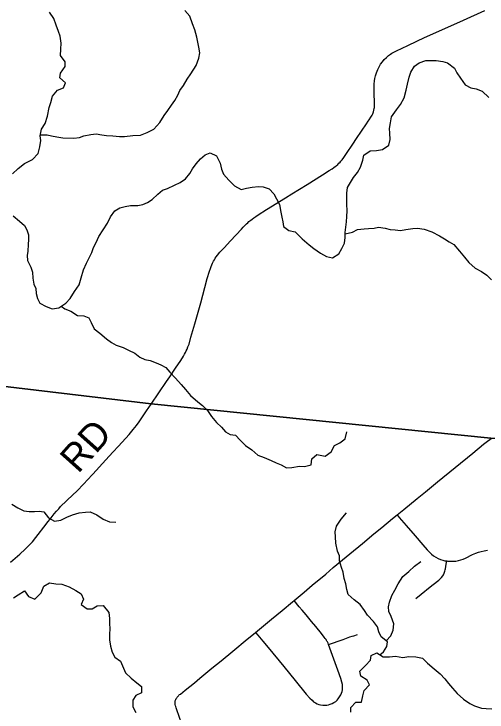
# Model space of a CAD drawing. Extents: x 0 to 34, y 0 to 22.
# Drawn here: x 6.899 to 7.881, y 18.658 to 20.107 of the extents above; entities that cross this region are included whole.
import ezdxf

# ---------------------------------------------------------------- set-up
doc = ezdxf.new("R2010")
doc.units = 0
for name, color, linetype in [('GM_X_Major_River', 7, 'Continuous'), ('GM_X_Minor_River', 7, 'Continuous'), ('GM_X_Township_Road', 7, 'Continuous'), ('GM_X_Township_Road_Text', 7, 'Continuous')]:
    doc.layers.add(name, color=color, linetype=linetype)

msp = doc.modelspace()

# ---------------------------------------------------------------- linework, layer by layer
at = {"layer": 'GM_X_Major_River'}
for points in [[(7.6639, 19.8257), (7.6766, 19.8342), (7.6795, 19.8463), (7.6787, 19.8592), (7.6785, 19.8691), (7.6806, 19.8809), (7.6824, 19.8934), (7.6926, 19.9076), (7.7008, 19.9185), (7.7084, 19.9328), (7.7125, 19.9483), (7.7158, 19.9607), (7.7192, 19.9755), (7.7228, 19.9857), (7.7303, 19.9981), (7.7399, 20.0051), (7.7533, 20.0101), (7.7655, 20.0102), (7.7753, 20.0097), (7.7886, 20.0082), (7.7988, 20.0054), (7.8129, 19.994), (7.818, 19.9844), (7.8258, 19.9732), (7.835, 19.9597), (7.847, 19.953), (7.8583, 19.9509), (7.8707, 19.9461), (7.8841, 19.9329)], [(6.9293, 19.6485), (6.9291, 19.639), (6.9281, 19.6283), (6.9274, 19.6147), (6.9261, 19.6052), (6.9266, 19.5953), (6.9339, 19.5814), (6.9375, 19.5707), (6.9383, 19.5585), (6.9403, 19.5463), (6.9439, 19.5368), (6.9452, 19.5268), (6.9473, 19.5165), (6.9528, 19.5065), (6.9655, 19.4998), (6.9779, 19.495), (6.992, 19.497), (7.0067, 19.5069), (7.0152, 19.5166), (7.0246, 19.5305), (7.0344, 19.5444), (7.0386, 19.5591), (7.0431, 19.5761), (7.0495, 19.5893), (7.0542, 19.5991), (7.0602, 19.6115), (7.0642, 19.6224), (7.0694, 19.6322), (7.075, 19.645), (7.084, 19.6585), (7.0927, 19.6728), (7.099, 19.6859), (7.108, 19.6983), (7.1188, 19.7041), (7.1299, 19.707), (7.1409, 19.709), (7.1561, 19.7094), (7.1664, 19.7115), (7.176, 19.7151), (7.1856, 19.7214), (7.1972, 19.7325), (7.2073, 19.7407), (7.2172, 19.7447), (7.2318, 19.7512), (7.2437, 19.757), (7.2545, 19.7644), (7.2638, 19.7756), (7.2694, 19.7854), (7.2768, 19.7959), (7.2858, 19.8059), (7.2958, 19.8145), (7.3058, 19.8184), (7.3193, 19.8125), (7.3266, 19.7971), (7.3293, 19.7845), (7.3336, 19.7741), (7.3448, 19.7621), (7.3566, 19.7497), (7.3705, 19.7422), (7.3816, 19.745), (7.3934, 19.747), (7.406, 19.7487), (7.4158, 19.7481), (7.4283, 19.7436), (7.4379, 19.7332), (7.4437, 19.7232), (7.4496, 19.7112), (7.453, 19.6952), (7.4551, 19.6849), (7.4567, 19.6754), (7.4584, 19.6654), (7.4693, 19.6572), (7.4825, 19.6543), (7.4973, 19.6399), (7.5115, 19.6278), (7.5212, 19.62), (7.5347, 19.6106), (7.5478, 19.6035), (7.5599, 19.601), (7.5733, 19.609), (7.5793, 19.6203), (7.5845, 19.6312), (7.5862, 19.6426), (7.5865, 19.6529), (7.5875, 19.6646), (7.5888, 19.6752), (7.5895, 19.6863), (7.5901, 19.6984), (7.59, 19.7121), (7.5896, 19.7254), (7.5894, 19.7349), (7.5912, 19.7463), (7.5975, 19.7572), (7.6038, 19.7673), (7.6116, 19.7774), (7.6179, 19.7887), (7.6228, 19.8034), (7.6249, 19.8136), (7.6384, 19.8228), (7.6509, 19.8233), (7.6639, 19.8257)], [(6.8971, 19.6879), (6.9105, 19.6766), (6.9206, 19.668), (6.9257, 19.6584), (6.9293, 19.6485)]]:
    msp.add_lwpolyline(points, dxfattribs=at)
at = {"layer": 'GM_X_Minor_River'}
for points in [[(6.9536, 19.856), (6.9675, 19.8555), (6.977, 19.8539), (6.9876, 19.8519), (7.0001, 19.8495), (7.0228, 19.8492), (7.0346, 19.8506), (7.0441, 19.8539), (7.0586, 19.8568), (7.0696, 19.8582), (7.081, 19.8561), (7.0912, 19.8541), (7.1041, 19.8536), (7.1178, 19.8523), (7.128, 19.8526), (7.1455, 19.8546), (7.1615, 19.8548), (7.1756, 19.8607), (7.1889, 19.8674), (7.2013, 19.8817), (7.2102, 19.8961), (7.2182, 19.9062), (7.2256, 19.9175), (7.2325, 19.9273), (7.2387, 19.9379), (7.2434, 19.9477), (7.2504, 19.9579), (7.2581, 19.9711), (7.2658, 19.982), (7.2767, 19.9998), (7.2826, 20.0149), (7.2846, 20.0259), (7.2824, 20.0373), (7.2807, 20.048), (7.2785, 20.0582), (7.2741, 20.0735), (7.2694, 20.0861), (7.2635, 20.1017), (7.2537, 20.114)], [(6.8955, 19.7747), (6.9074, 19.7863), (6.9205, 19.7964), (6.9373, 19.8046), (6.9492, 19.8174), (6.9524, 19.8306), (6.9544, 19.8439), (6.953, 19.8538), (6.9562, 19.8674), (6.9636, 19.8795), (6.9683, 19.8946), (6.972, 19.9125), (6.9755, 19.9227), (6.9787, 19.9363), (6.9891, 19.9487), (7.0017, 19.9535), (7.006, 19.9637), (6.9943, 19.9741), (6.9952, 19.984), (7.0052, 19.9972), (7.0054, 20.007), (6.9953, 20.0201), (6.9962, 20.0337), (6.9967, 20.0459), (6.9946, 20.0607), (6.9909, 20.0703), (6.9865, 20.0832), (6.9814, 20.097), (6.9728, 20.1104)], [(7.5864, 19.6502), (7.6017, 19.6542), (7.6116, 19.6594), (7.6253, 19.6607), (7.6348, 19.6618), (7.6462, 19.6624), (7.6557, 19.6642), (7.6693, 19.6625), (7.6799, 19.6597), (7.6898, 19.6588), (7.7008, 19.6576), (7.7122, 19.6593), (7.7266, 19.6618), (7.7365, 19.6621), (7.7502, 19.6604), (7.7664, 19.6545), (7.7823, 19.646), (7.7921, 19.6398), (7.8022, 19.634), (7.812, 19.6282), (7.8233, 19.6148), (7.8341, 19.6017), (7.8431, 19.591), (7.8562, 19.5794), (7.8691, 19.5721), (7.88, 19.5644), (7.8897, 19.5551)], [(6.9971, 19.5004), (7.0042, 19.4946), (7.017, 19.4899), (7.0306, 19.481), (7.0439, 19.4805), (7.0541, 19.4762), (7.0593, 19.4663), (7.0652, 19.4533), (7.0772, 19.4444), (7.0911, 19.4325), (7.1013, 19.4251), (7.1111, 19.4197), (7.1255, 19.4146), (7.1364, 19.4088), (7.15, 19.4029), (7.1598, 19.3948), (7.1707, 19.3901), (7.1813, 19.3874), (7.1938, 19.3827), (7.2036, 19.3787), (7.2142, 19.3733), (7.2224, 19.3637), (7.2344, 19.351), (7.2456, 19.3376), (7.255, 19.3273), (7.2655, 19.315), (7.2801, 19.3023), (7.2903, 19.2942), (7.3004, 19.2838), (7.309, 19.2712), (7.3195, 19.2589), (7.3292, 19.2497), (7.3375, 19.2397), (7.3473, 19.2339), (7.3583, 19.233), (7.368, 19.2223), (7.3796, 19.2115), (7.3928, 19.2022), (7.4052, 19.1911), (7.4181, 19.1864), (7.4324, 19.1805), (7.443, 19.1751), (7.4532, 19.1711), (7.4641, 19.1649), (7.4755, 19.1659), (7.4915, 19.1688), (7.5021, 19.1679), (7.5154, 19.1716), (7.5171, 19.1837), (7.5275, 19.1927), (7.5445, 19.1891), (7.5571, 19.1981), (7.5641, 19.2113), (7.5752, 19.2168), (7.5863, 19.2255), (7.5899, 19.2395)], [(6.8946, 19.0894), (6.907, 19.0824), (6.9191, 19.0758), (6.9305, 19.0746), (6.9411, 19.0748), (6.951, 19.0751), (6.9608, 19.0738), (6.9705, 19.0612), (6.983, 19.0542), (6.9959, 19.0563), (7.0085, 19.0627), (7.0204, 19.0675), (7.0344, 19.0719), (7.047, 19.0728), (7.0572, 19.0739), (7.0705, 19.0676), (7.0836, 19.0588), (7.0969, 19.0533), (7.1105, 19.0524)], [(7.6585, 18.7772), (7.6657, 18.7835), (7.673, 18.7944), (7.6743, 18.8039), (7.6608, 18.8147), (7.6559, 18.825), (7.653, 18.8349), (7.6452, 18.846), (7.6328, 18.8595), (7.6261, 18.8691), (7.6171, 18.8813), (7.6047, 18.8913), (7.5927, 18.9021), (7.5898, 18.9124), (7.5873, 18.9242), (7.584, 18.9356), (7.5823, 18.9486), (7.5786, 18.9581), (7.5746, 18.9722), (7.5743, 18.9825), (7.5703, 18.9924), (7.5666, 19.0088), (7.5661, 19.0221), (7.5654, 19.032), (7.5682, 19.0441), (7.5779, 19.0588), (7.589, 19.0716)], [(7.6713, 18.8063), (7.6809, 18.8168), (7.686, 18.8285), (7.6869, 18.8414), (7.6818, 18.857), (7.6766, 18.867), (7.6759, 18.8768), (7.6779, 18.8863), (7.6834, 18.8999), (7.6892, 18.9116), (7.6962, 18.9245), (7.7059, 18.9396), (7.7185, 18.9497), (7.7301, 18.9613), (7.7435, 18.9707)], [(6.8976, 18.8956), (6.9075, 18.9016), (6.9209, 18.9102), (6.9287, 18.8979), (6.9424, 18.8929), (6.955, 18.906), (6.9609, 18.9196), (6.9727, 18.9263), (6.9856, 18.9246), (6.9981, 18.9234), (7.0136, 18.9179), (7.0272, 18.9105), (7.0381, 18.9039), (7.0429, 18.8928), (7.0386, 18.8815), (7.0507, 18.8726), (7.0609, 18.8729), (7.0716, 18.8785), (7.0842, 18.8798), (7.0958, 18.8649), (7.0971, 18.8523), (7.097, 18.8428), (7.0976, 18.8303), (7.0971, 18.8208), (7.097, 18.8083), (7.0991, 18.7949), (7.1024, 18.7824), (7.1083, 18.772), (7.1196, 18.7643), (7.1263, 18.7498), (7.1303, 18.7399), (7.142, 18.7287), (7.1536, 18.7191), (7.1634, 18.7114), (7.1632, 18.6981), (7.1514, 18.6929), (7.1456, 18.6831), (7.1458, 18.6694), (7.1517, 18.6576)], [(7.5978, 18.6582), (7.5979, 18.6677), (7.6083, 18.6789), (7.62, 18.6788), (7.6232, 18.6921), (7.6253, 18.7034), (7.6364, 18.7147), (7.6316, 18.7246), (7.6184, 18.7328), (7.6166, 18.7434), (7.6282, 18.7547), (7.6385, 18.766), (7.6402, 18.7755), (7.652, 18.781), (7.6652, 18.7733), (7.6781, 18.7727), (7.691, 18.7741), (7.7058, 18.7717), (7.7183, 18.7738), (7.7331, 18.7732), (7.7468, 18.77), (7.7573, 18.7597), (7.7712, 18.7481), (7.7832, 18.7377), (7.7933, 18.7277), (7.8004, 18.7174), (7.809, 18.7078), (7.8188, 18.6967), (7.8315, 18.6851), (7.8447, 18.6759), (7.8545, 18.6712), (7.8689, 18.6665), (7.8791, 18.6656), (7.8905, 18.6651)]]:
    msp.add_lwpolyline(points, dxfattribs=at)
at = {"layer": 'GM_X_Township_Road'}
msp.add_lwpolyline([(8.9, 19.1426), (8.9, 20.9), (4.4664, 20.9), (4.4684, 20.7448), (4.4849, 19.6021), (5.1411, 19.5203), (5.6889, 19.4592), (5.8809, 19.4409), (6.3561, 19.3959), (7.1834, 19.2978), (7.8888, 19.2268), (8.4186, 19.1875)], close=True, dxfattribs=at)
for points in [[(7.1836, 19.2972), (7.2156, 19.3439), (7.2226, 19.3541), (7.2342, 19.3718), (7.2448, 19.3879), (7.2504, 19.3969), (7.2525, 19.4006), (7.2548, 19.4045), (7.2565, 19.4079), (7.2581, 19.4112), (7.26, 19.4158), (7.261, 19.4187), (7.2621, 19.4217), (7.2662, 19.4361), (7.2742, 19.4635), (7.2865, 19.5072), (7.2949, 19.539), (7.3, 19.5576), (7.3046, 19.5731), (7.3065, 19.5788), (7.3078, 19.5824), (7.3094, 19.5862), (7.3109, 19.5898), (7.313, 19.5937), (7.3147, 19.5968), (7.3166, 19.5998), (7.3184, 19.6025), (7.3209, 19.6059), (7.326, 19.6121), (7.3348, 19.6217), (7.3484, 19.6362), (7.3708, 19.6604), (7.3748, 19.6644), (7.3786, 19.6684), (7.3814, 19.6711), (7.384, 19.6734), (7.3866, 19.6757), (7.3901, 19.6786), (7.3933, 19.6811), (7.3969, 19.6839), (7.4005, 19.6864), (7.4056, 19.6898), (7.423, 19.7006), (7.4621, 19.7248), (7.4758, 19.7333), (7.5075, 19.7529), (7.5391, 19.7725), (7.5533, 19.7815), (7.5589, 19.7852), (7.5627, 19.7877), (7.5655, 19.7899), (7.5676, 19.7916), (7.571, 19.7945), (7.5732, 19.7968), (7.5757, 19.7994), (7.5774, 19.8013), (7.5798, 19.8042), (7.5836, 19.8091), (7.5889, 19.8168), (7.6018, 19.8366), (7.6097, 19.8485), (7.6304, 19.8787), (7.634, 19.8838), (7.6361, 19.8869), (7.6395, 19.8921), (7.642, 19.8968), (7.6434, 19.8993), (7.6451, 19.9037), (7.646, 19.9071), (7.6465, 19.9101), (7.647, 19.9127), (7.6473, 19.9159), (7.6473, 19.9193), (7.6474, 19.9234), (7.6466, 19.9408), (7.6463, 19.952), (7.6465, 19.9606), (7.6471, 19.968), (7.6479, 19.9728), (7.649, 19.9782), (7.651, 19.9847), (7.6538, 19.9915), (7.6565, 19.997), (7.6597, 20.0022), (7.6634, 20.0071), (7.6674, 20.0118), (7.6717, 20.0163), (7.6762, 20.0204), (7.6801, 20.0233), (7.6832, 20.0252), (7.6925, 20.0299), (7.7162, 20.0409), (7.7352, 20.0501), (7.751, 20.0574), (7.7992, 20.0789), (7.8315, 20.0935), (7.8762, 20.1136)], [(8.9, 16.5763), (8.9, 19.1426), (8.4186, 19.1875), (7.8888, 19.2268), (7.1834, 19.2978), (6.3561, 19.3959), (5.8809, 19.4409), (5.6889, 19.4592), (5.1411, 19.5203), (4.4849, 19.6021), (4.4789, 19.5742), (4.3389, 18.9527), (4.2897, 18.7747), (4.1943, 18.4289), (4.1901, 18.4135), (4.0744, 17.9948), (3.9903, 17.6899), (3.7921, 17.074)], [(6.8916, 18.9693), (6.9108, 18.986), (6.9223, 18.9965), (6.9261, 19.0002), (6.9298, 19.0039), (6.9336, 19.008), (6.937, 19.0117), (6.9442, 19.0203), (6.9657, 19.0484), (6.9693, 19.0529), (6.9737, 19.0585), (6.9783, 19.0644), (6.9825, 19.0695), (6.9874, 19.0754), (6.9917, 19.0802), (6.9957, 19.0846), (7.0076, 19.0963), (7.0217, 19.1095), (7.0284, 19.1159), (7.0445, 19.1323), (7.0508, 19.1392), (7.0624, 19.1522), (7.0897, 19.1818), (7.1037, 19.1976), (7.1155, 19.2103), (7.1378, 19.2345), (7.1464, 19.2444), (7.153, 19.2527), (7.1585, 19.2602), (7.1741, 19.2834), (7.1836, 19.2972)], [(7.6938, 19.0676), (7.7079, 19.0789), (7.7357, 19.1017), (7.7526, 19.1155), (7.7776, 19.1359), (7.8514, 19.1958), (7.8736, 19.2138), (7.8789, 19.218), (7.8891, 19.2262)], [(7.4002, 18.8236), (7.4333, 18.8509), (7.4552, 18.8692), (7.4768, 18.8869), (7.4804, 18.89), (7.501, 18.9074), (7.518, 18.9218), (7.5458, 18.9448), (7.5612, 18.9583), (7.5956, 18.9868), (7.6221, 19.0084), (7.646, 19.0282), (7.6624, 19.0416), (7.6842, 19.0599), (7.6938, 19.0676)], [(7.6938, 19.0676), (7.6985, 19.0622), (7.7127, 19.0457), (7.7314, 19.0241), (7.7475, 19.0052), (7.7564, 18.9948), (7.7611, 18.9899), (7.7653, 18.9861), (7.7697, 18.9827), (7.7744, 18.9797), (7.7793, 18.977), (7.7839, 18.9751), (7.7886, 18.9735), (7.7934, 18.9723), (7.7972, 18.9718)], [(7.7972, 18.9718), (7.7983, 18.9716), (7.8039, 18.9712), (7.8101, 18.9712), (7.8157, 18.9716), (7.8212, 18.9725), (7.8266, 18.9739), (7.8313, 18.9756), (7.8359, 18.9776), (7.8508, 18.9853), (7.8542, 18.9868), (7.8576, 18.9883), (7.8628, 18.9903), (7.8682, 18.9918), (7.8749, 18.9932), (7.8816, 18.9941)], [(7.733, 18.8942), (7.744, 18.9033), (7.7624, 18.918), (7.7775, 18.9299), (7.7803, 18.9322), (7.7827, 18.9343), (7.7847, 18.9362), (7.7863, 18.9378), (7.7886, 18.9407), (7.7902, 18.9433), (7.7918, 18.9466), (7.7926, 18.9487), (7.7933, 18.9507), (7.794, 18.9532), (7.7945, 18.9555), (7.7961, 18.9653), (7.7972, 18.9718)], [(7.5517, 18.7984), (7.5506, 18.8011), (7.5493, 18.8038), (7.5485, 18.8054), (7.5478, 18.8067), (7.5465, 18.8088), (7.5448, 18.8113), (7.5428, 18.8141), (7.5372, 18.8213), (7.525, 18.8361), (7.5163, 18.8466), (7.5053, 18.86), (7.4967, 18.8698), (7.4909, 18.877), (7.4804, 18.89)], [(7.2517, 18.6219), (7.237, 18.6629), (7.2354, 18.6675), (7.2347, 18.6697), (7.2341, 18.6716), (7.2337, 18.674), (7.2333, 18.6763), (7.2332, 18.6787), (7.2335, 18.6814), (7.234, 18.6831), (7.2349, 18.6848), (7.2357, 18.6864), (7.2367, 18.6879), (7.2377, 18.6894), (7.2389, 18.6907), (7.2401, 18.6921), (7.2413, 18.6932), (7.2427, 18.6946), (7.2441, 18.6959), (7.2544, 18.7039), (7.2733, 18.7191), (7.2848, 18.7286), (7.3096, 18.7492), (7.3285, 18.7644), (7.3528, 18.7847), (7.3831, 18.8094), (7.3959, 18.8201), (7.4002, 18.8236)], [(7.4002, 18.8236), (7.4049, 18.8179), (7.4151, 18.8054), (7.4262, 18.7921), (7.4586, 18.7528), (7.4705, 18.7384), (7.4824, 18.7241), (7.5056, 18.6958), (7.513, 18.6874), (7.5174, 18.6829), (7.5208, 18.68), (7.5245, 18.6775), (7.5279, 18.6758), (7.5315, 18.6744), (7.5352, 18.6735), (7.5396, 18.6729), (7.5434, 18.6727), (7.5479, 18.6729), (7.5516, 18.6736), (7.5553, 18.6746), (7.5595, 18.6763), (7.5628, 18.6781), (7.5665, 18.6807), (7.5693, 18.6833), (7.5719, 18.6861), (7.5745, 18.6897), (7.5771, 18.6941), (7.5787, 18.6975), (7.5799, 18.7012), (7.5807, 18.7049), (7.581, 18.7081), (7.5809, 18.7113), (7.5804, 18.7157), (7.5794, 18.7207), (7.5772, 18.7279), (7.571, 18.7455), (7.5517, 18.7984)], [(7.5517, 18.7984), (7.5823, 18.8091), (7.5962, 18.8142), (7.6007, 18.8157), (7.6044, 18.8169), (7.6118, 18.8196)]]:
    msp.add_lwpolyline(points, dxfattribs=at)

# ---------------------------------------------------------------- texts
at = {"layer": 'GM_X_Township_Road_Text'}
msp.add_text('RD', height=0.05682, rotation=48.246, dxfattribs=at).set_placement((7.032, 19.1515))

doc.saveas('drawing.dxf')
